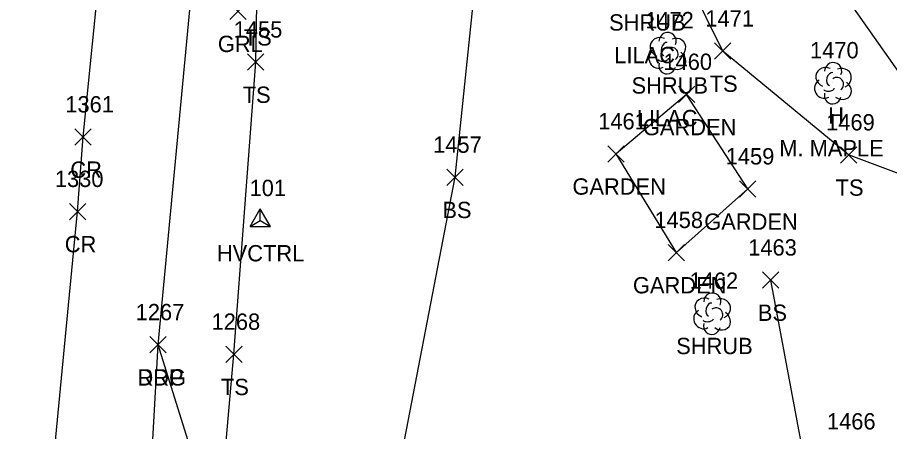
# Model space of a CAD drawing. Extents: x 1653908 to 1654393, y 539913 to 544256.
# Drawn here: x 1654041 to 1654147.8, y 541422.7 to 541473.4 of the extents above; entities that cross this region are included whole.
import ezdxf

# ---------------------------------------------------------------- set-up
doc = ezdxf.new("R2010")
doc.units = 0
for name, color, linetype in [('C_A', 7, 'Continuous'), ('C_I', 7, 'Continuous'), ('CPSM', 7, 'Continuous'), ('L_A', 7, 'Continuous'), ('L_C', 7, 'Continuous'), ('L_I', 7, 'Continuous'), ('L_TIC', 7, 'Continuous'), ('LAPB', 7, 'Continuous'), ('LAWA', 7, 'Continuous'), ('LELB', 7, 'Continuous'), ('LSH', 7, 'Continuous'), ('LTD', 7, 'Continuous'), ('P_A', 7, 'Continuous'), ('P_I', 7, 'Continuous'), ('P_TIC', 7, 'Continuous'), ('PET', 7, 'Continuous'), ('PRC', 7, 'Continuous'), ('R_A', 7, 'Continuous'), ('R_I', 7, 'Continuous'), ('R_TIC', 7, 'Continuous'), ('RDG', 7, 'Continuous')]:
    doc.layers.add(name, color=color, linetype=linetype)

msp = doc.modelspace()

# ---------------------------------------------------------------- linework, layer by layer
at = {"layer": 'CPSM'}
for p, q in [((1654069.51, 541447.77), (1654070.76, 541449.94)), ((1654072.01, 541447.77), (1654070.76, 541449.94)), ((1654070.76, 541448.5), (1654070.76, 541449.94)), ((1654069.51, 541447.77), (1654070.76, 541448.5)), ((1654069.51, 541447.77), (1654072.01, 541447.77)), ((1654070.76, 541448.5), (1654070.76, 541448.5)), ((1654070.76, 541448.5), (1654072.01, 541447.77))]:
    msp.add_line(p, q, dxfattribs=at)
at = {"layer": 'L_TIC'}
for points in [[(1654126.36, 541468.26), (1654128.36, 541470.26)], [(1654128.36, 541468.26), (1654126.36, 541470.26)], [(1654069.2, 541466.91), (1654071.2, 541468.91)], [(1654071.2, 541466.91), (1654069.2, 541468.91)], [(1654121.93, 541462.95), (1654123.93, 541464.95)], [(1654123.93, 541462.95), (1654121.93, 541464.95)], [(1654113.3, 541455.67), (1654115.3, 541457.67)], [(1654115.3, 541455.67), (1654113.3, 541457.67)], [(1654113.3, 541455.67), (1654115.3, 541457.67)], [(1654115.3, 541455.67), (1654113.3, 541457.67)], [(1654141.77, 541455.54), (1654143.77, 541457.54)], [(1654143.77, 541455.54), (1654141.77, 541457.54)], [(1654093.61, 541452.8), (1654095.61, 541454.8)], [(1654095.61, 541452.8), (1654093.61, 541454.8)], [(1654129.43, 541451.37), (1654131.43, 541453.37)], [(1654131.43, 541451.37), (1654129.43, 541453.37)], [(1654120.7, 541443.58), (1654122.7, 541445.58)], [(1654122.7, 541443.58), (1654120.7, 541445.58)], [(1654120.7, 541443.58), (1654122.7, 541445.58)], [(1654122.7, 541443.58), (1654120.7, 541445.58)], [(1654132.22, 541440.21), (1654134.22, 541442.21)], [(1654134.22, 541440.21), (1654132.22, 541442.21)], [(1654066.54, 541431.12), (1654068.54, 541433.12)], [(1654068.54, 541431.12), (1654066.54, 541433.12)]]:
    msp.add_lwpolyline(points, dxfattribs=at)
at = {"layer": 'LAPB'}
for points in [[(1654121.7, 541444.58), (1654130.43, 541452.37), (1654122.93, 541463.95), (1654114.3, 541456.67)], [(1654121.7, 541444.58), (1654114.3, 541456.67)]]:
    msp.add_lwpolyline(points, dxfattribs=at)
at = {"layer": 'LAWA'}
msp.add_lwpolyline([(1654160.84, 541449.79), (1654138.36, 541481.73), (1654119.3, 541498.08), (1654124, 541512.09), (1654120.71, 541524.25), (1654111.1, 541539.43)], dxfattribs=at)
at = {"layer": 'LELB'}
for points in [[(1654065.55, 541409.89), (1654067.54, 541432.12), (1654070.2, 541467.91), (1654070.34, 541474.94), (1654070.4, 541508.69), (1654072.4, 541525.84), (1654075.32, 541545.16), (1654075.45, 541573)], [(1654160.84, 541449.79), (1654142.77, 541456.54), (1654127.36, 541469.26), (1654113.22, 541497.93)], [(1654131.27, 541408.59), (1654106.78, 541414.13), (1654086.76, 541412.9), (1654094.61, 541453.8), (1654098.52, 541491.53)], [(1654133.22, 541441.21), (1654138.12, 541415.03), (1654141.31, 541405.29)]]:
    msp.add_lwpolyline(points, dxfattribs=at)
at = {"layer": 'LSH'}
for p, q in [((1654120.57, 541469.05), (1654120.57, 541469.05)), ((1654120.57, 541469.05), (1654120.57, 541469.05)), ((1654126.04, 541437.14), (1654126.04, 541437.14)), ((1654126.04, 541437.14), (1654126.04, 541437.14))]:
    msp.add_line(p, q, dxfattribs=at)
for centre in [(1654120.61, 541470.49), (1654126.09, 541438.58)]:
    msp.add_arc(centre, 1.05, 335.5272, 180.9563, dxfattribs=at)
for centre, major_axis, ratio, start_param, end_param in [((1654119.77, 541469.72), (1.21, -0.51), 0.895232, 1.570796, 4.712389), ((1654120.36, 541469.51), (-0.208, -0.792), 0.645439, 3.141593, 6.283185), ((1654121.61, 541469.64), (-1.14, -0.48), 0.949671, 1.570796, 4.712389), ((1654119.48, 541468.35), (0.58, -1.04), 0.959034, 3.141593, 6.283185), ((1654121.07, 541468.89), (-0.5, 0.667), 0.989748, 3.141593, 6.283185), ((1654121.57, 541468.22), (-1.09, 0.79), 0.841452, 1.570796, 4.712389), ((1654120.11, 541468.3), (-0.625, -0.083), 0.423636, 0, 3.141593), ((1654120.57, 541467.55), (0.26, 1.06), 0.942809, 1.570796, 4.712389), ((1654125.25, 541437.81), (1.21, -0.51), 0.895232, 1.570796, 4.712389), ((1654125.84, 541437.6), (-0.208, -0.792), 0.645439, 3.141593, 6.283185), ((1654127.09, 541437.73), (-1.14, -0.48), 0.949671, 1.570796, 4.712389), ((1654124.96, 541436.43), (0.58, -1.04), 0.959034, 3.141593, 6.283185), ((1654126.54, 541436.98), (-0.5, 0.667), 0.989748, 3.141593, 6.283185), ((1654127.04, 541436.31), (-1.09, 0.79), 0.841452, 1.570796, 4.712389), ((1654125.59, 541436.39), (-0.625, -0.083), 0.423636, 0, 3.141593), ((1654126.04, 541435.64), (0.26, 1.06), 0.942809, 1.570796, 4.712389)]:
    msp.add_ellipse(centre, major_axis=major_axis, ratio=ratio, start_param=start_param, end_param=end_param, dxfattribs=at)
at = {"layer": 'LTD'}
msp.add_line((1654140.83, 541465.37), (1654140.83, 541465.37), dxfattribs=at)
msp.add_line((1654140.83, 541465.37), (1654140.83, 541465.37), dxfattribs=at)
msp.add_arc((1654140.88, 541466.81), 1.05, 335.5272, 180.9563, dxfattribs=at)
for centre, major_axis, ratio, start_param, end_param in [((1654140.04, 541466.04), (1.21, -0.51), 0.895232, 1.570796, 4.712389), ((1654141.88, 541465.96), (-1.14, -0.48), 0.949671, 1.570796, 4.712389), ((1654140.63, 541465.83), (-0.208, -0.792), 0.645439, 3.141593, 6.283185), ((1654141.33, 541465.21), (-0.5, 0.667), 0.989748, 3.141593, 6.283185), ((1654139.75, 541464.66), (0.58, -1.04), 0.959034, 3.141593, 6.283185), ((1654141.83, 541464.54), (-1.09, 0.79), 0.841452, 1.570796, 4.712389), ((1654140.83, 541463.87), (0.26, 1.06), 0.942809, 1.570796, 4.712389), ((1654140.38, 541464.62), (-0.625, -0.083), 0.423636, 0, 3.141593)]:
    msp.add_ellipse(centre, major_axis=major_axis, ratio=ratio, start_param=start_param, end_param=end_param, dxfattribs=at)
at = {"layer": 'P_TIC'}
for points in [[(1654048.07, 541457.74), (1654050.07, 541459.74)], [(1654050.07, 541457.74), (1654048.07, 541459.74)], [(1654047.4, 541448.61), (1654049.4, 541450.61)], [(1654049.4, 541448.61), (1654047.4, 541450.61)], [(1654057.25, 541432.29), (1654059.25, 541434.29)], [(1654059.25, 541432.29), (1654057.25, 541434.29)]]:
    msp.add_lwpolyline(points, dxfattribs=at)
at = {"layer": 'PET'}
msp.add_lwpolyline([(1654026.62, 541021.77), (1654028.54, 541070.24), (1654031.49, 541127.98), (1654037.66, 541208.54), (1654042.53, 541248.32), (1654044.37, 541265.21), (1654043.73, 541271.44), (1654047, 541298.33), (1654052.52, 541346.47), (1654054.45, 541365.83), (1654058.25, 541433.29), (1654064.32, 541497.28)], dxfattribs=at)
at = {"layer": 'PRC'}
msp.add_lwpolyline([(1654015.22, 541022.42), (1654016.68, 541078.09), (1654019.78, 541129.03), (1654023.08, 541180.04), (1654025.54, 541208.79), (1654028.97, 541248.66), (1654033.81, 541299.54), (1654044.55, 541409.64), (1654048.4, 541449.61), (1654049.07, 541458.74), (1654052.54, 541493.4), (1654055.94, 541523.17), (1654060.18, 541564.47), (1654062.59, 541587.52)], dxfattribs=at)
at = {"layer": 'R_TIC'}
for points in [[(1654067.03, 541473.14), (1654069.03, 541475.14)], [(1654069.03, 541473.14), (1654067.03, 541475.14)], [(1654057.25, 541432.29), (1654059.25, 541434.29)], [(1654059.25, 541432.29), (1654057.25, 541434.29)]]:
    msp.add_lwpolyline(points, dxfattribs=at)
at = {"layer": 'RDG'}
msp.add_lwpolyline([(1654070.6, 541383.17), (1654069.87, 541391.54), (1654065.55, 541409.89), (1654058.25, 541433.29)], dxfattribs=at)

# ---------------------------------------------------------------- texts
at = {"layer": 'C_A'}
msp.add_text('HVCTRL', height=2, dxfattribs=at).set_placement((1654065.45, 541443.5))
at = {"layer": 'C_I'}
msp.add_text('101', height=2, dxfattribs=at).set_placement((1654069.45, 541451.5))
at = {"layer": 'L_A'}
for s, p in [('SHRUB', (1654113.45, 541471.77)), ('TS', (1654068.75, 541469.94)), ('SHRUB', (1654116.2, 541464.05)), ('TS', (1654125.77, 541464.26)), ('TS', (1654068.61, 541462.91)), ('H', (1654140.27, 541460.37)), ('GARDEN', (1654117.59, 541458.95)), ('GARDEN', (1654108.97, 541451.67)), ('GARDEN', (1654108.97, 541451.67)), ('TS', (1654141.18, 541451.54)), ('BS', (1654093.05, 541448.8)), ('GARDEN', (1654125.1, 541447.37)), ('GARDEN', (1654116.37, 541439.58)), ('GARDEN', (1654116.37, 541439.58)), ('BS', (1654131.66, 541436.21)), ('SHRUB', (1654121.67, 541432.14)), ('TS', (1654065.95, 541427.12))]:
    msp.add_text(s, height=2, dxfattribs=at).set_placement(p)
at = {"layer": 'L_C'}
for s, p in [('LILAC', (1654114.09, 541467.77)), ('LILAC', (1654116.84, 541460.05)), ('M. MAPLE', (1654134.28, 541456.37))]:
    msp.add_text(s, height=2, dxfattribs=at).set_placement(p)
at = {"layer": 'L_I'}
for s, p in [('1472', (1654117.87, 541472.05)), ('1471', (1654125.24, 541472.26)), ('1455', (1654067.51, 541470.91)), ('1470', (1654138.05, 541468.37)), ('1460', (1654120.1, 541466.95)), ('1461', (1654112.12, 541459.67)), ('1461', (1654112.12, 541459.67)), ('1469', (1654140.02, 541459.54)), ('1457', (1654091.92, 541456.8)), ('1459', (1654127.73, 541455.37)), ('1458', (1654119, 541447.58)), ('1458', (1654119, 541447.58)), ('1463', (1654130.48, 541444.21)), ('1462', (1654123.3, 541440.14)), ('1268', (1654064.8, 541435.12)), ('1466', (1654140.12, 541422.91))]:
    msp.add_text(s, height=2, dxfattribs=at).set_placement(p)
at = {"layer": 'P_A'}
for s, p in [('CR', (1654047.51, 541453.74)), ('CR', (1654046.83, 541444.61)), ('RDP', (1654055.73, 541428.29))]:
    msp.add_text(s, height=2, dxfattribs=at).set_placement(p)
at = {"layer": 'P_I'}
for s, p in [('1361', (1654046.9, 541461.74)), ('1330', (1654045.62, 541452.61)), ('1267', (1654055.51, 541436.29))]:
    msp.add_text(s, height=2, dxfattribs=at).set_placement(p)
at = {"layer": 'R_A'}
for s, p in [('GRL', (1654065.57, 541469.14)), ('DRG', (1654055.73, 541428.29))]:
    msp.add_text(s, height=2, dxfattribs=at).set_placement(p)
at = {"layer": 'R_I'}
msp.add_text('1267', height=2, dxfattribs=at).set_placement((1654055.51, 541436.29))

doc.saveas('drawing.dxf')
